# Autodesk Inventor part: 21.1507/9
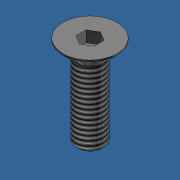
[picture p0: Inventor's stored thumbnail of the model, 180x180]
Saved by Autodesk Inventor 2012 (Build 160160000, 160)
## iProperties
Created: 2006-12
Part Number: 21.1507/9
Material: Steel, Mild
Description: M6X20 C'SUNK BLACK
Document SubType Name: Modeling
Standard: DIN 7991
Designer: Andy Moles
Standards Organization: DIN
Language: en-US
Size Designation: M6x20
Categories: <MemberInstance Version="R10.0.0"><Categories><Category DisplayName="Fasteners" InternalName="e4da775c-781d-43d5-af7c-5136215cf5a6" Mnemonic="FSTN"><Category Di
Mass: 5.2442 g
Surface Area: 6.15988 cm^2
Volume: 0.667201 cm^3
Density: 7.86 g/cm^3
Vendor: S
Author: Andy Moles
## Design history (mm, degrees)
node "Sketch1"
node "WorkPoint1"
sketch "Sketch2"
  geometry: L1 (-3, -20)-(0, -20); L2 (-3, -3.3)-(-3, -20); L3 (-6, -0.3)-(-3, -3.3); L4 (-6, 0)-(-6, -0.3); L5 (0, 0)-(-6, 0); L6 (0, -20)-(0, 0); L7 (0, -20)-(0, 0); L8 (0, -22)-(0, 6) reference; L9 (0.6, 0)-(-7.8, 0) reference
  constraints: 14 end point, 3 vertical, 2 horizontal
  dimensions: "d1" = 45 deg angle of L3 L6; "d3" = 6 distance of L5.start L4.start (= 0.5 x dk); "d5" = 3 distance of L1.start L1.end (= 0.5 x NND); "d7" = 20 distance of L1.end L5.start (= NLG); "ParC" = 0.3 distance of L4.start L3.start; "d22" = 0 distance between parallel lines of L8 L6; "d23" = 0 distance between parallel lines of L9 L5
fillet "Fillet1" dims "d18" = 0.3 (= r)
chamfer "Chamfer1" distance "d19" = 0.5 (= 0.5 x PTC); stored, may be unused: angle "d20" = 45 deg, second distance "d39" = 0.5 (= 0.5 x PTC)
node "MSC_A1"
node "MSC_PF1"
node "MSC_PT1"
body "Solid1"
revolve "Revolution1" stored, may be unused: angle "d8" = 360 deg
sketch "Sketch3"
  geometry: L1 (-2, 1.155)-(-2, -1.155); L2 (0, 2.309)-(-2, 1.155); L3 (2, 1.155)-(0, 2.309); L4 (2, -1.155)-(2, 1.155); L5 (0, -2.309)-(2, -1.155); L6 (-2, -1.155)-(0, -2.309); C1 r 2 at (0, 0); C2 r 3 at (0, 0) reference
  constraints: 12 end point, 6 tangent, 2 parallel, 2 vertical, 1 centre point, 1 concentric
  dimensions: "d11" = 4 diameter of C1 (= ParS); "d13" = 120 deg angle of L1 L2; "d15" = 120 deg angle of L6 L1
extrude "Extrusion1" cut sketch "Sketch3" distance "d16" = 2.5 (= ParT); taper "d17" = 0 deg
thread "Thread1" dims "d35" = 0, "b" = 14.7
other parameters: "NND" = 6 [user parameter; used in 2 equation terms], "PTC" = 1 [user parameter; used in 2 equation terms], "dk" = 12 [user parameter; used in 1 equation term], "ParK" = 3.3 [user parameter], "ParS" = 4 [user parameter; used in 1 equation term], "ParT" = 2.5 [user parameter; used in 1 equation term], "r" = 0.3 [user parameter; used in 1 equation term], "NLG" = 20 [user parameter; used in 1 equation term], "d0" = 45 deg (derived), "d2" = 3 (derived), "d4" = 1.5 (derived), "d6" = 8 (derived), "d9" = 0, "d10" = 2 (derived), "d12" = 120 deg (derived), "d14" = 120 deg (derived), "d37" = 0, "d38" = 0, "d40" = 0, "d41" = 0, "d42" = 0, "THREADDIA" = 6 (= NND) [user parameter]
